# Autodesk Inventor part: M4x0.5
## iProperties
IsCustomPart: 1
Company: 한국ATC센터
Created: 2014-11
Part Number: M4x0.5
Material: 강, 연강
Description: 6각머리 태핑 나사
Document SubType Name: Modeling
Standard: KS B 1003
Designer: KYOUNG IL JANG
Standards Organization: KS
Language: ko-KR
Size Designation: M 4 x 16
Categories: <MemberInstance><Categories><Category DisplayName="조임쇠" InternalName="e4da775c-781d-43d5-af7c-5136215cf5a6" Mnemonic="FSTN"><Category DisplayName="볼트" InternalN
Density: 7.86 g/cm^3
Mass: 2.62973 g
Surface Area: 3.81119 cm^2
Volume: 0.334572 cm^3
Author: KYOUNG IL JANG
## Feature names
1. Fillet2
